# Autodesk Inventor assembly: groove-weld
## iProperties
Created: 2005-03
Part Number: groove-weld
Document SubType Name: Weldment
Designer: CADCIM
Manufacturer: Standard
Standards Organization: Custom
Author: CADCIM
